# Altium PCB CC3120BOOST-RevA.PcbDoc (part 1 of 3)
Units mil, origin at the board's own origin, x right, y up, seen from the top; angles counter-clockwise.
Board outline 2300 x 1700 mil, 4 copper layers (Top Layer, Mid-Layer 1, Mid-Layer 2, Bottom Layer), stack 90 mil thick; 155 components, 108 nets, 432 pads, 292 vias.
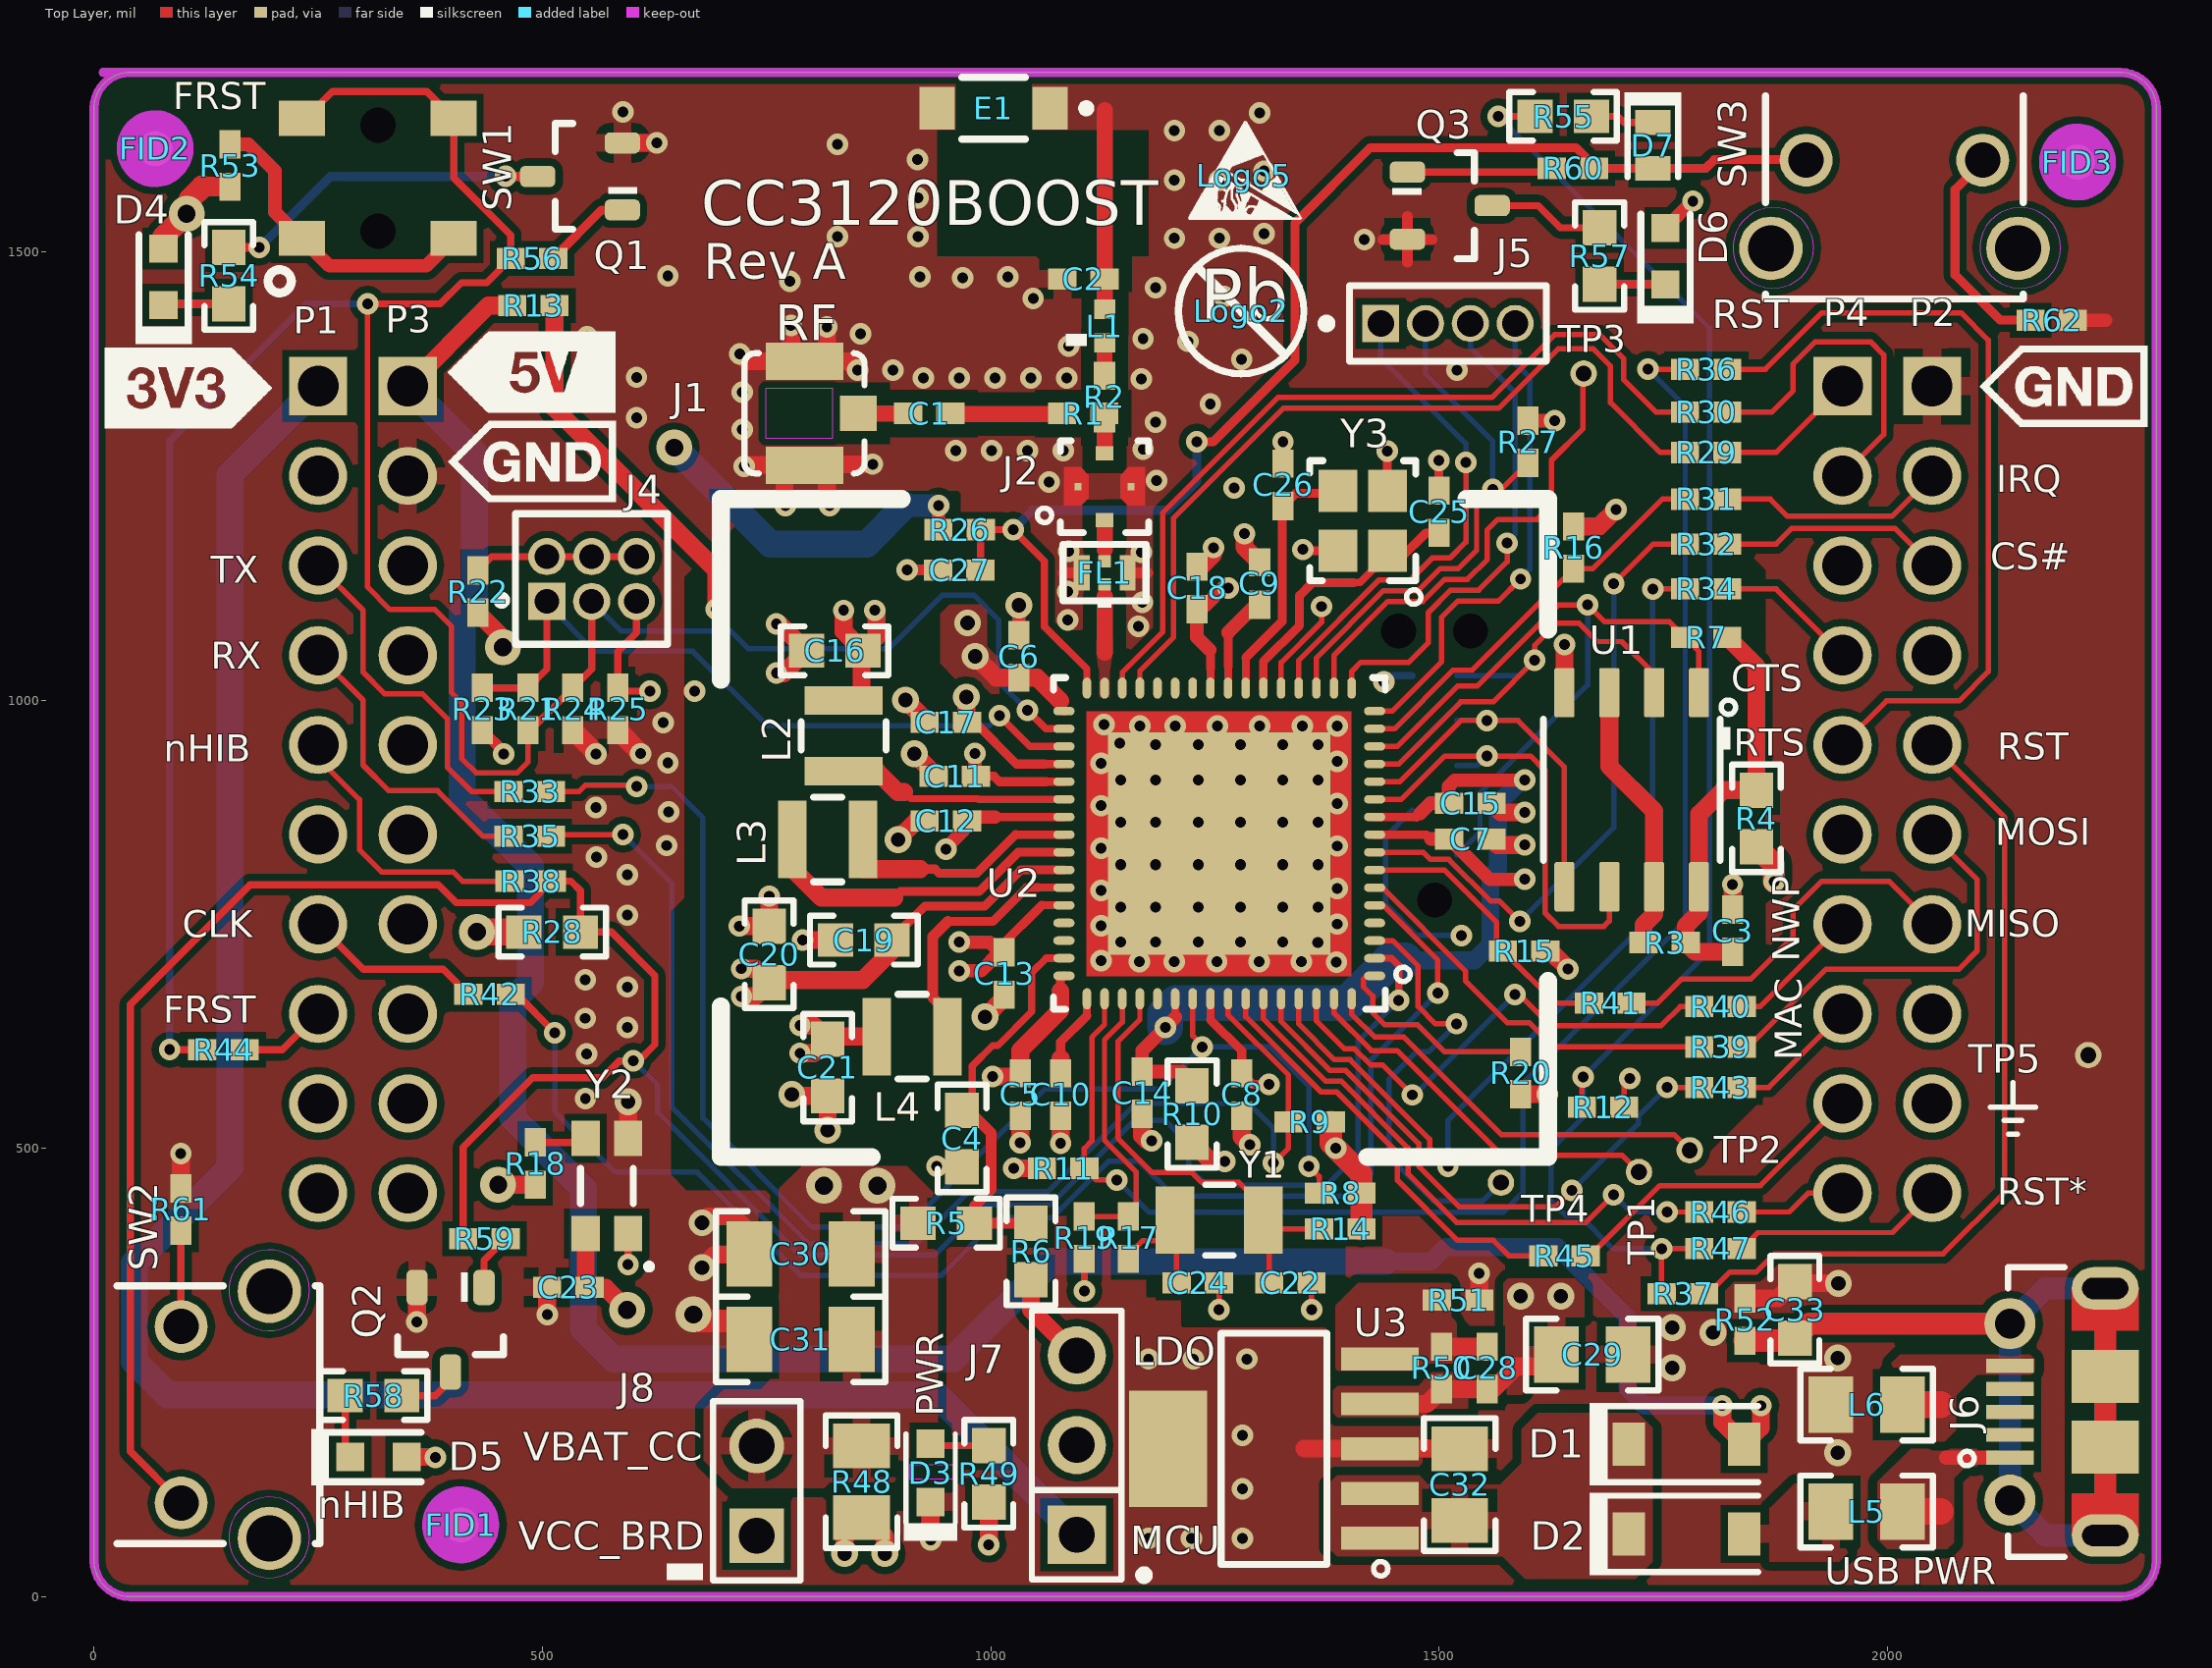
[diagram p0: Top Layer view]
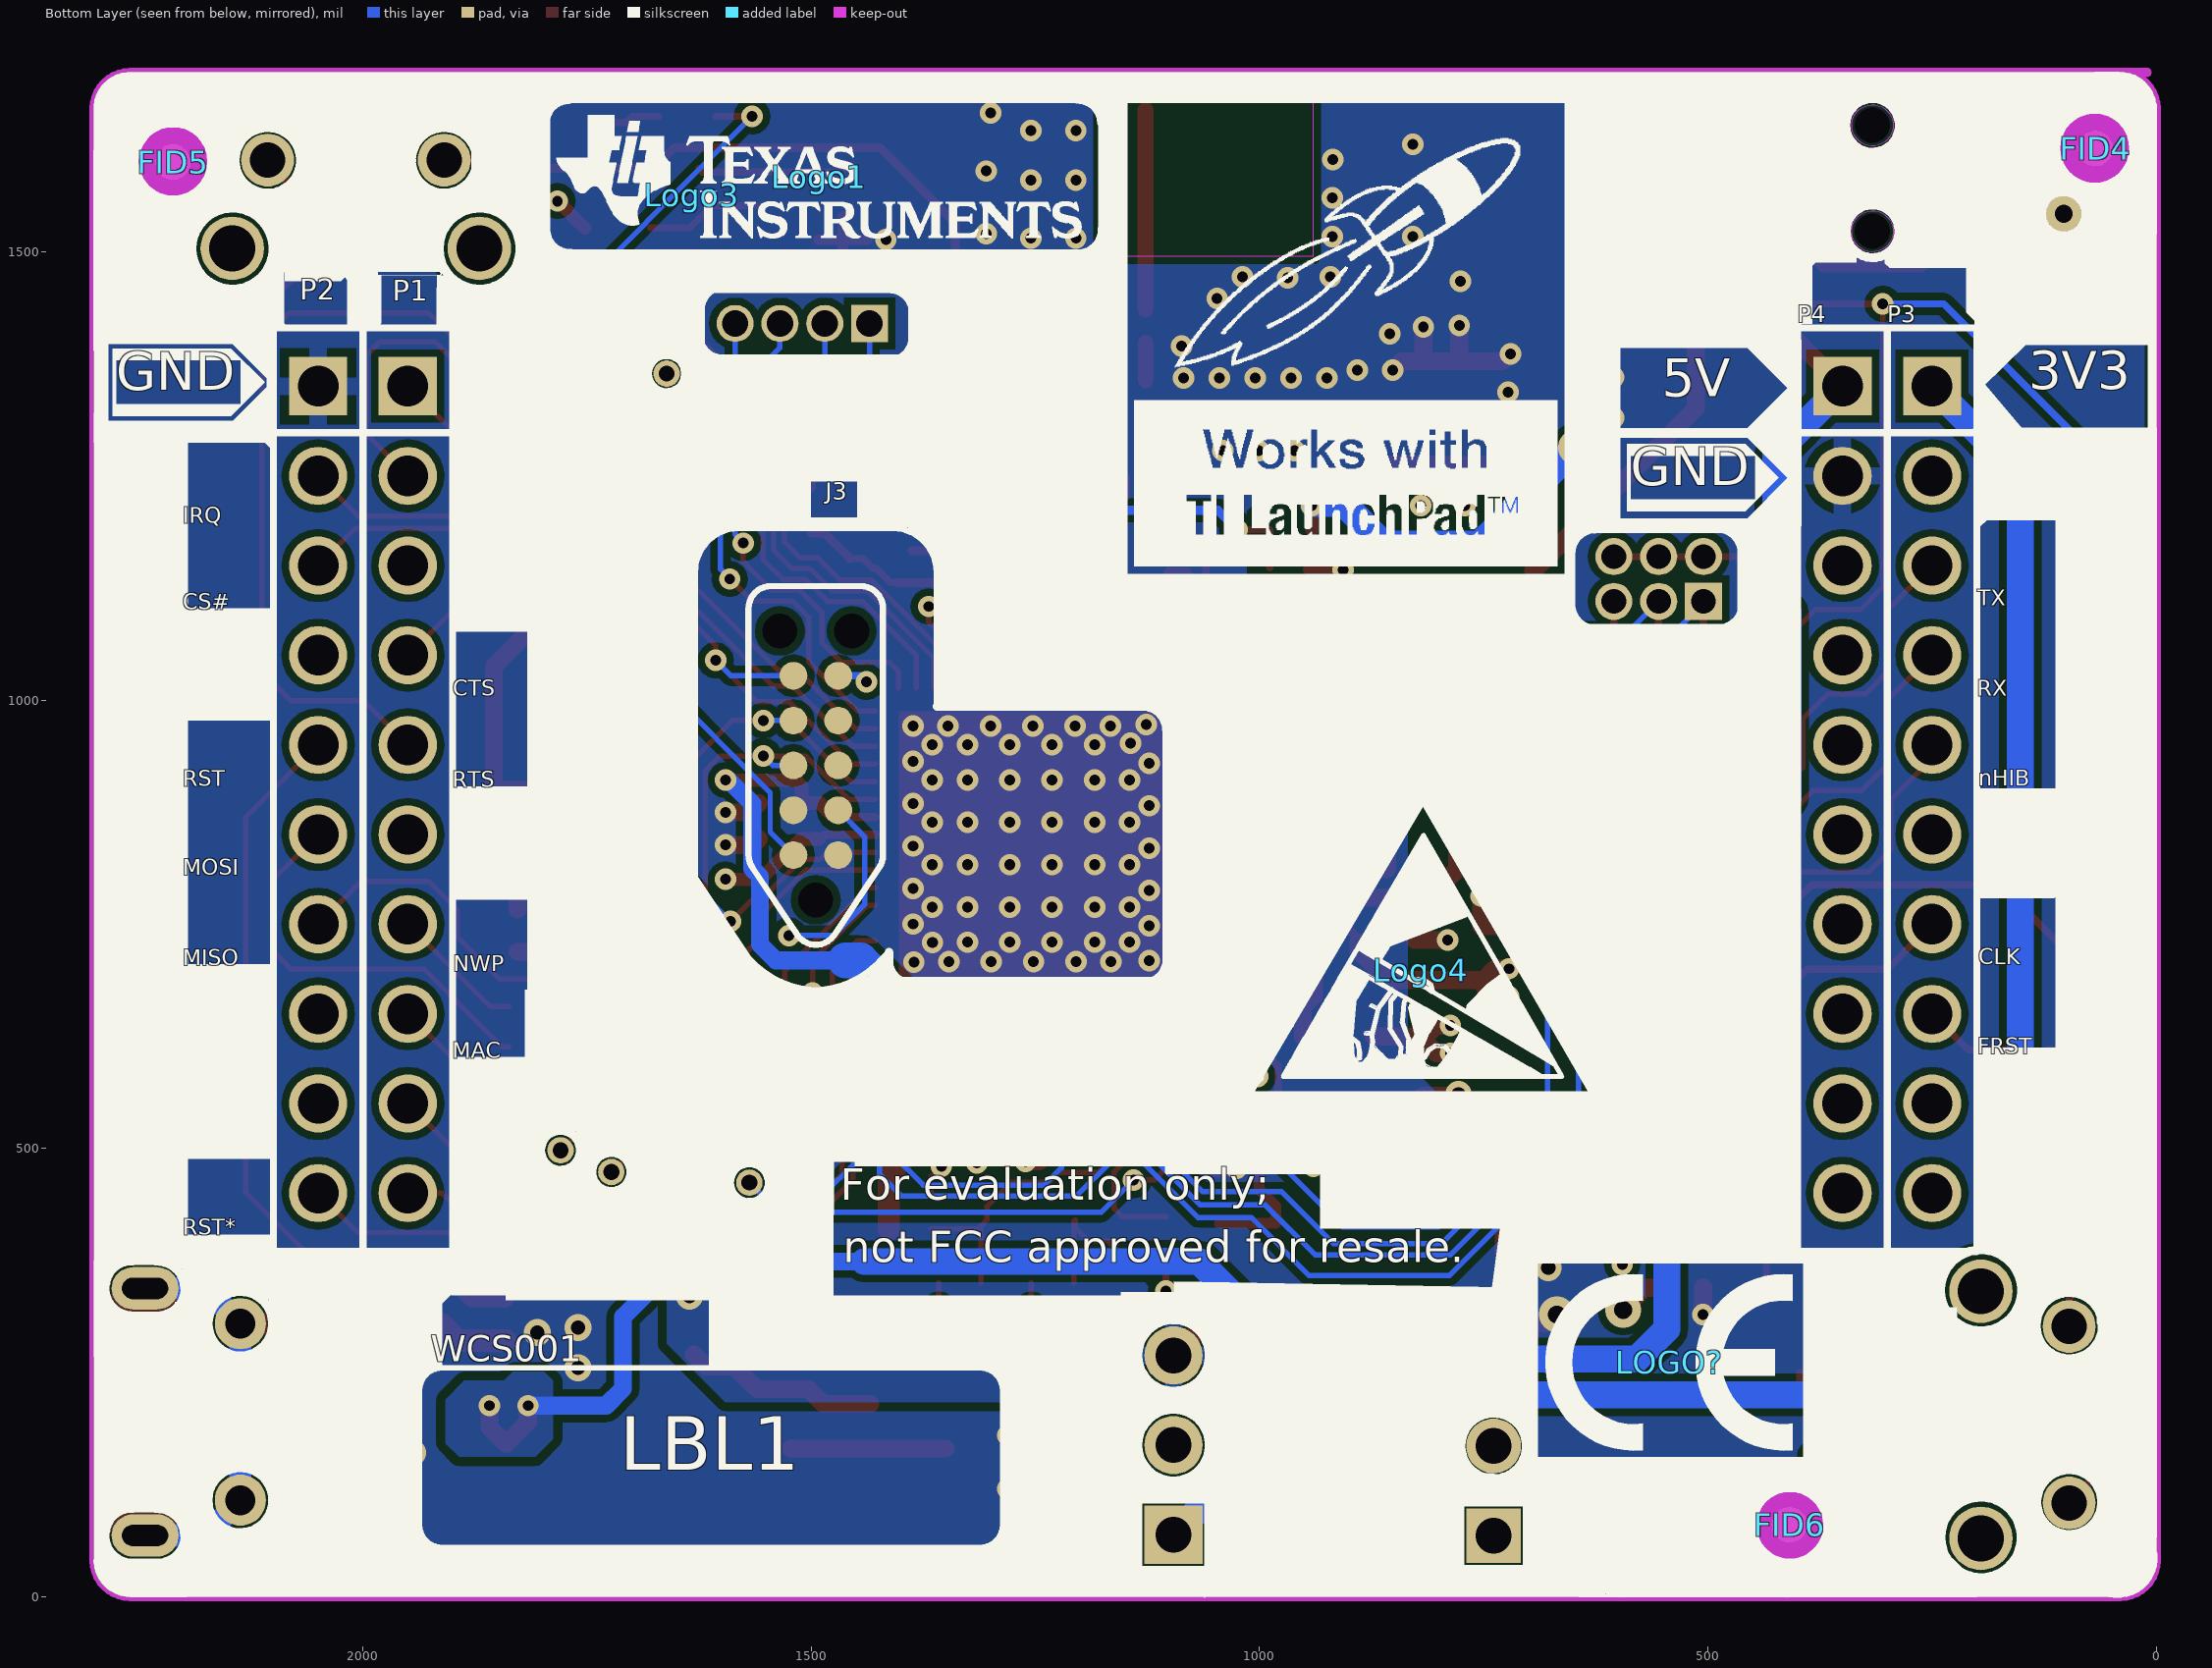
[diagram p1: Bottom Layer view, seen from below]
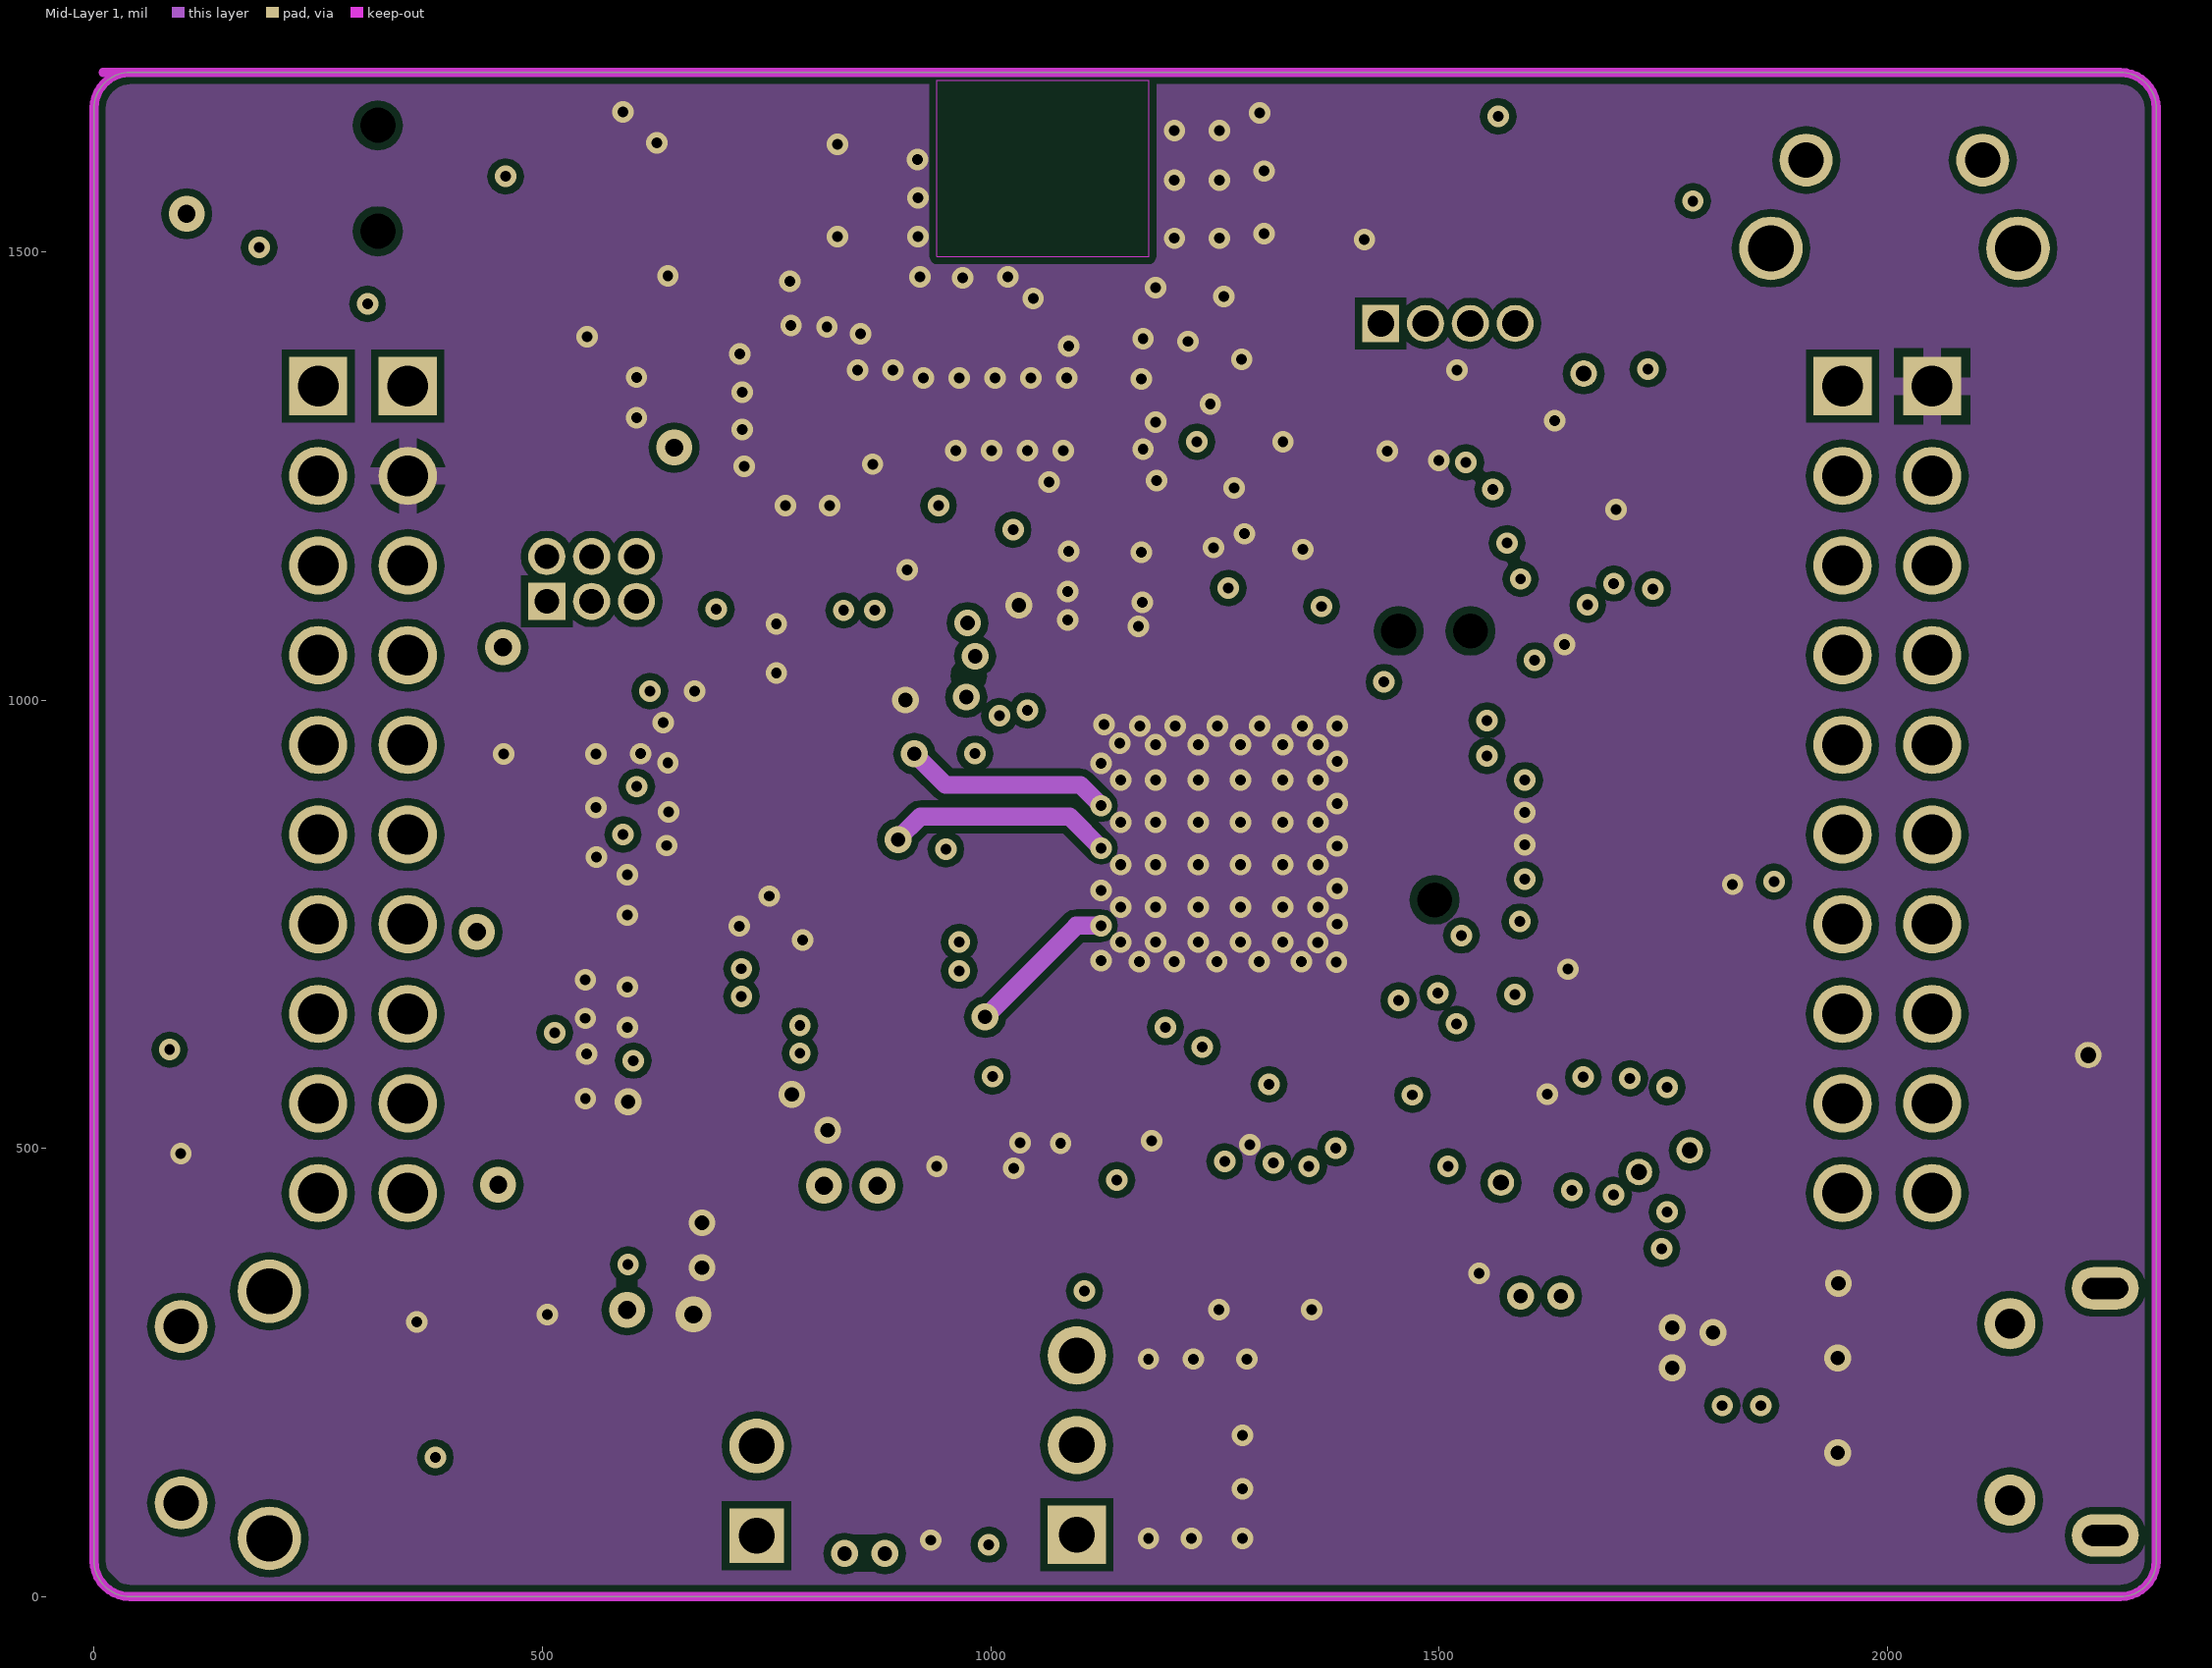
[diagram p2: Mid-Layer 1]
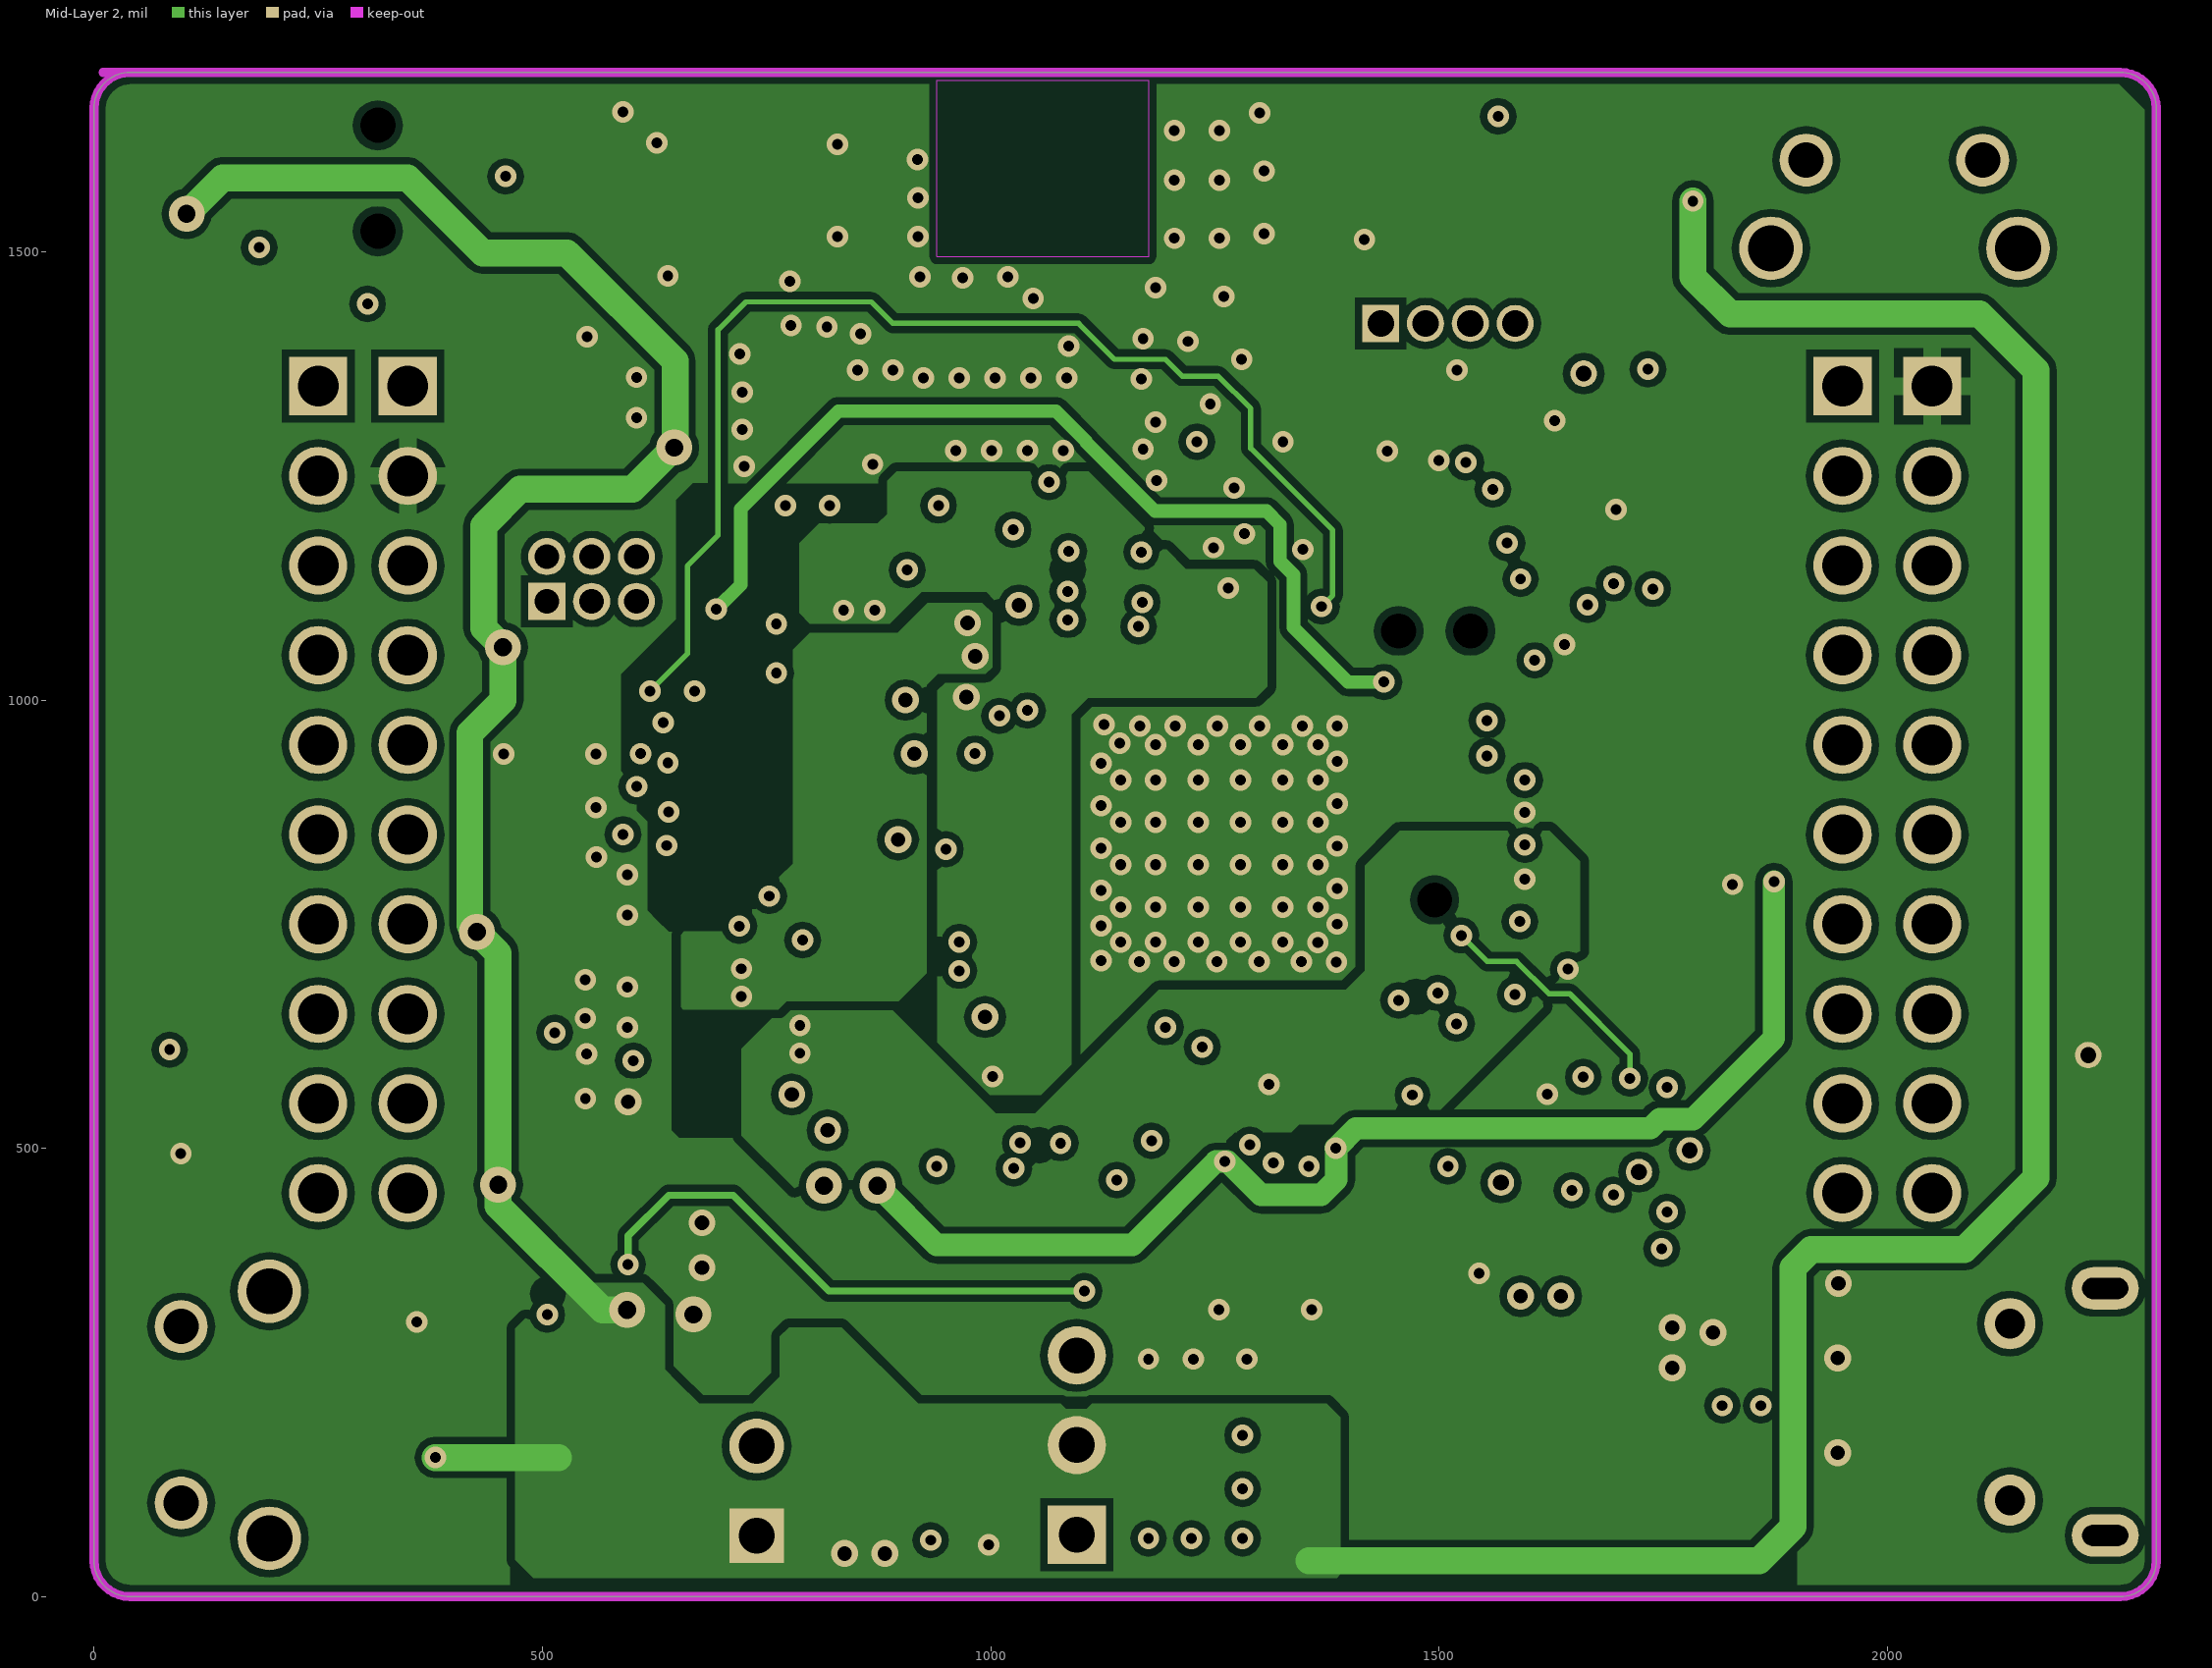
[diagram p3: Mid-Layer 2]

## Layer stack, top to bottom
Top Solder: solder mask 0.4, Solder Resist, Dk 3.5
Top Layer: signal copper 1.4
Dielectric1: core 59.2, FR-4, Dk 4.8
Mid-Layer 1: signal copper 1.4
Dielectric2: dielectric 12.6, FR-4, Dk 4.8
Mid-Layer 2: signal copper 1.4
Dielectric3: dielectric 12.6, FR-4, Dk 4.8
Bottom Layer: signal copper 1.4
Bottom Solder: solder mask 0.4, Solder Resist, Dk 3.5

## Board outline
0,40 ccw(c40,40) 40,0 2260,0 ccw(c2260,40) 2300,40 2300,1660 ccw(c2260,1660) 2260,1700 40,1700 ccw(c40,1660) 0,1660

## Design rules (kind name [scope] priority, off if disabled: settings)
AcuteAngle [All] p1: minimum=4.50000000000000E+0001 checktracksonly=TRUE
AssemblyTestPointUsage [All] p1: valid=2
Clearance Clearance_3 [InNetClass('50 ohm') vs INPOLY] p1: gap=15
Clearance Clearance_1 [inpoly vs inpoly] p2: gap=10
Clearance Clearance_Poly [InPolygon] p3: gap=7.9
Clearance Clearance_2 [iskeepout] p4: gap=0
Clearance [All] p5: gap=6
ComponentClearance ComponentClearance_MountingHoles_FiducialMarks [InComponentClass('Mounting Holes') vs InComponentClass('FiducialMark')] p1: gap=10 collisioncheckmode=3 verticalgap=10 showdistances=FALSE
ComponentClearance ComponentClearance_Shunt [InComponentClass('Header') vs InComponentClass('Shunt')] p2: gap=0 collisioncheckmode=3 verticalgap=0 showdistances=FALSE
ComponentClearance ComponentClearance_Logo [InComponentClass('Logo')] p3: gap=0 collisioncheckmode=3 verticalgap=0 showdistances=FALSE
ComponentClearance ComponentClearance_ScrewToNut [(HasFootprint('NY PMS 440 0025 PH')) vs (HasFootprint('Keystone_1902C'))] p4: gap=0 collisioncheckmode=3 verticalgap=0 showdistances=FALSE
ComponentClearance ComponentClearance_MountingHoles [InComponentClass('Mounting Holes')] p5: gap=20 collisioncheckmode=3 verticalgap=100000 showdistances=FALSE
ComponentClearance ComponentClearance_SmallPassives [HasFootprint('0201*') or HasFootprint('0402*') or HasFootprint('0508') or HasFootprint('0603*') or HasFootprint('0612') or HasFootprint('0805*') or HasFootprint('0815*') or HasFootprint('0830*') or HasFootprint('1206*') or HasFootprint('1210*') or HasFootprint('1808*') or HasFootprint('1812*') or HasFootprint('1825*') or HasFootprint('2010*') or HasFootprint('2220*') or HasFootprint('2225*') or HasFootprint('2512*') or HasFootprint('2728*') or HasFootprint('3518*') vs HasFootprint('0201*') or HasFootprint('0402*') or HasFootprint('0508') or HasFootprint('0603*') or HasFootprint('0612') or HasFootprint('0805*') or HasFootprint('0815*') or HasFootprint('0830*') or HasFootprint('1206*') or HasFootprint('1210*') or HasFootprint('1808*') or HasFootprint('1812*') or HasFootprint('1825*') or HasFootprint('2010*') or HasFootprint('2220*') or HasFootprint('2225*') or HasFootprint('2512*') or HasFootprint('2728*') or HasFootprint('3518*')] p6 off: gap=10 collisioncheckmode=3 verticalgap=10 showdistances=FALSE
ComponentClearance ComponentClearance_THtoSMT [IsThruComponent vs IsSMTComponent] p7: gap=10 collisioncheckmode=3 verticalgap=10 showdistances=FALSE
ComponentClearance ComponentClearance_THtoTH [IsThruComponent vs IsThruComponent] p8: gap=0 collisioncheckmode=3 verticalgap=10 showdistances=FALSE
ComponentClearance [All] p9 off: gap=10 collisioncheckmode=3 verticalgap=10 showdistances=FALSE
DiffPairsRouting [All] p1: maxlimit=100 minlimit=10 mostfreqgap=10 toplayer_minwidth=15 toplayer_maxwidth=15 toplayer_prefwidth=15 midlayer1_minwidth=15 midlayer1_maxwidth=15 midlayer1_prefwidth=15 midlayer2_minwidth=15 midlayer2_maxwidth=15 midlayer2_prefwidth=15 bottomlayer_minwidth=15 bottomlayer_maxwidth=15 bottomlayer_prefwidth=15 maxuncoupledlength=1000
FabricationTestPointUsage TestPointUsage [All] p1: valid=2 allowmultiple=FALSE
FabricationTestpoint Testpoint [All] p1: side=3 testpointundercomponent=TRUE minsize=40 maxsize=100 preferedsize=60 minholesize=0 maxholesize=40 preferedholesize=32 testpointgrid=1 allowsidetop=TRUE allowsidebottom=TRUE usegrid=TRUE gridtolerance=0.01
FanoutControl Fanout_LCC [IsLCC] p1: bgadir=Out bgaviamode=Centered fanoutstyle=Auto fanoutdirection=Alternating viagrid=1 // Fanout_LCC (Default Rule)
FanoutControl Fanout_BGA [IsBGA] p2: bgadir=Out bgaviamode=Centered fanoutstyle=Auto fanoutdirection=Alternating viagrid=1 // Fanout_BGA (Default Rule)
FanoutControl Fanout_Default [All] p4: bgadir=Out bgaviamode=Centered fanoutstyle=Auto fanoutdirection=Alternating viagrid=1 // Fanout_Default (Default Rule)
FanoutControl Fanout_Small [(CompPinCount < 5)] p5: bgadir=Out bgaviamode=Centered fanoutstyle=Auto fanoutdirection=OutThenIn viagrid=1 // Fanout_Small (Default Rule)
Height [All] p1: minheight=0 maxheight=1345 prefheight=500
HoleSize [All] p1: absolutevalues=TRUE maxlimit=251 minlimit=8 maxpercent=80.000 minpercent=20.000
MinimumAnnularRing MinimumAnnularRing_ThermalPadVias [IsVia and InAnyComponent] p1: minimumring=5
MinimumAnnularRing [All] p2: minimumring=5
MinimumSolderMaskSliver MinimumSolderMaskSliver_Logo [InComponentClass('Logo') vs InComponentClass('Logo')] p1: minsoldermaskwidth=0.7
MinimumSolderMaskSliver [All] p2: minsoldermaskwidth=3
PlaneConnect [All] p1: planeconnectstyle=Relief reliefexpansion=10 reliefentries=4 reliefconductorwidth=10 reliefairgap=10
PolygonConnect PolygonConnect_3 [InPadClass('SMD')] p1: connectstyle=Relief reliefconductorwidth=20 reliefentries=4 polygonreliefangle="90 Angle" airgapwidth=10
PolygonConnect [InPadClass('TH')] p2: connectstyle=Relief reliefconductorwidth=20 reliefentries=4 polygonreliefangle="90 Angle" airgapwidth=10
PolygonConnect PolygonConnect_1 [InPadClass('PLANECLASS')] p3: connectstyle=Direct reliefconductorwidth=10 reliefentries=4 polygonreliefangle="90 Angle" airgapwidth=10
PolygonConnect PolygonConnect_2 [All] p4: connectstyle=Direct reliefconductorwidth=10 reliefentries=4 polygonreliefangle="90 Angle" airgapwidth=10
RoutingVias ThermalPadVias [IsVia and InAnyComponent] p1: holewidth=7.87 width=24 viastyle="Through Hole" minholewidth=7.87 minwidth=24 maxholewidth=12.99 maxwidth=24
RoutingVias [All] p2: holewidth=16 width=34 viastyle="Through Hole" minholewidth=7.87 minwidth=24 maxholewidth=40 maxwidth=65
SilkToSilkClearance SilkToSilkClearance_Pb-FreeLogo [(HasFootprint('Pb-Free_Overlay_Medium') OR HasFootprint('Pb-Free_Overlay_Small')) vs (HasFootprint('Pb-Free_Overlay_Medium') OR HasFootprint('Pb-Free_Overlay_Small'))] p1: silktosilkclearance=0
SilkToSilkClearance [All] p2: silktosilkclearance=3
SilkToSolderMaskClearance "Silk to Solder Mask Opening" [IsPad] p1: minsilkscreentomaskgap=1 clearancetoexposedcopper=TRUE
SolderMaskExpansion SolderMaskExpansion_1 [InPadClass('SM')] p1: expansion=2.5
SolderMaskExpansion [All] p2: expansion=0
Width [All] p1: maxlimit=100 minlimit=6 preferedwidth=10 checkconnectedcopper=TRUE
15 further rules are at their usual default settings.

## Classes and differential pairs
pad class SMD: C2-1 C2-2 C3-1 C3-2 C4-1 C4-2 C5-1 C5-2 C6-1 C6-2 C7-1 C7-2 C9-1 C9-2 C10-1 C10-2 C11-1 C11-2 C12-1 C12-2 C13-1 C13-2 C14-1 C14-2 C16-1 C16-2 C18-1 C18-2 C20-1 C20-2 C21-1 C21-2 C22-1 C22-2 C23-1 C23-2 C25-1 C25-2 C26-1 C26-2 C27-1 C27-2 C28-1 C28-2 C29-1 C29-2 C30-1 C30-2 C31-1 C31-2 C32-1 C32-2 D3-1 D3-2 D4-1 D4-2 L7-1 L7-2 L8-1 L8-2 Q1-1 Q1-2 Q1-3 Q2-1 Q2-2 Q2-3 Q3-1 Q3-2 Q3-3 R2-1 R2-2 R3-1 R3-2 R4-1 R4-2 R5-1 R5-2 R6-1 R6-2 R7-1 R7-2 R8-1 R8-2 R10-1 R10-2 R11-1 R11-2 R12-1 R12-2 R13-1 R13-2 R14-1 R14-2 R15-1 R15-2 R16-1 R16-2 R17-1 R17-2 R18-1 R18-2 R19-1 R19-2 R20-1 R20-2 R21-1 R21-2 R22-1 R22-2 R23-1 R23-2 R24-1 R24-2 R25-1 R25-2 R26-1 R26-2 R28-1 R28-2 R29-1 R29-2 R31-1 R31-2 R32-1 R32-2 R33-1 R33-2 R34-1 R34-2 R36-1 R36-2 R38-1 R38-2 R39-1 R39-2 R40-1 R40-2 R41-1 R41-2 R42-1 R42-2 R43-1 R43-2 R44-1 R44-2 R45-1 R45-2 R46-1 R46-2 R48-1 R48-2 R54-1 R54-2 R55-1 R55-2 R56-1 R56-2 R57-1 R57-2 R58-1 R58-2 R59-1 R59-2 R60-1 R60-2 R286-1 R286-2 R290-1 R290-2 R295-1 R295-2 R297-1 R297-2 TP1-1 U4-6
pad class PLANECLASS: C1-1 C1-2 E1-1 E1-2 FL1-1 FL1-2 FL1-3 FL1-4 J2-1 J2-2 J2-3 J3-1 J3-2 J3-3
pad class "New Class": SW1-3 SW1-MH1
component class Logo: Logo1
component class Label: LBL1
component class Header: J4 J5 J7 J8
component class FiducialMark: FID1 FID2 FID3 FID4 FID5 FID6
component class AssemblyNote: ZZ2 ZZ3 ZZ4
pad class TH: J6-1 J6-2 J7-10 J7-11 J8-2 J8-3 P1-1 P1-2 P1-3 P1-4 P1-5 P1-6 P1-7 P1-8 P1-9 P1-10 P2-1 P2-2 P2-3 P2-4 P2-5 P2-6 P2-7 P2-8 P2-9 P2-10 P3-1 P3-2 P3-3 P3-4 P3-5 P3-6 P3-7 P3-8 P3-9 P3-10 P4-1 P4-2 P4-3 P4-4 P4-5 P4-6 P4-7 P4-8 P4-9 P4-10 SW2-1 SW2-2 SW3-1 SW3-2
component class 1.Engine: C1 C2 C3 C4 C5 C6 C7 C8 C9 C10 C11 C12 C13 C14 C15 C16 C17 C18 C19 C20 C21 C22 C23 C24 C25 C26 C27 E1 FL1 J1 J2 J3 J4 J5 L1 L2 L3 L4 R1 R2 R3 R4 R5 R6 R7 R8 R9 R10 R11 R12 R13 R14 R15 R16 R17 R18 R19 R20 R21 R22 R23 R24 R25 R26 R27 TP1 TP2 TP3 TP4 U1 U2 Y1 Y2 Y3
component class "2.HOST INTERFACE": C28 C29 C30 C31 C32 C33 D1 D2 D3 D4 D5 D6 D7 J6 J7 J8 L5 L6 P1 P2 P3 P4 Q1 Q2 Q3 R28 R29 R30 R31 R32 R33 R34 R35 R36 R37 R38 R39 R40 R41 R42 R43 R44 R45 R46 R47 R48 R49 R50 R51 R52 R53 R54 R55 R56 R57 R58 R59 R60 R61 R62 SW1 SW2 SW3 TP5 U3
pad class SM: J4-1 J4-2 J4-3 J4-4 J4-5 J4-6 J5-1 J5-2 J6-1 J6-2 J7-6 J7-9 J7-10 J7-11 J8-1 J8-2 J8-3
component class EVM_Hardware: FID1 FID2 FID3 FID4 FID5 FID6 LBL1 Logo1 Logo2 Logo3 Logo4 Logo5 LOGO? ZZ2 ZZ3 ZZ4
net class "50 ohm": NetC1_2 NetFL1_1 NetFL1_3 NetJ2_2

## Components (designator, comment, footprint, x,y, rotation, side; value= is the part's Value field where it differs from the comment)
C1 "500R07S100JV4T" 0402#1 931.5,1319.75 r180 top
C2 "GRM1555C1HR50BA01D" 0402#1 1103.43,1469.57 r0 top locked
C3 "C1005X5R1A104K050BA" 0402#1 1827.5,742.67 r90 top locked
C4 "GRM188R60J106ME47D" 0603 968,511 r270 top locked
C5 "C1005X5R1A104K050BA" 0402#1 1033,560 r270 top locked
C6 "C1005X5R1A105K050BB" 0402#1 1031.6,1048.7 r90 top
C7 "C1005X5R1A104K050BA" 0402#1 1535,845 r0 top locked
C8 "C1005X5R1A104K050BA" 0402#1 1280,560 r270 top locked
C9 "C1005X5R1A104K050BA" 0402#1 1300,1130 r90 top locked
C10 "C1005X5R1A104K050BA" 0402#1 1078,560 r270 top locked
C11 "C1005X5R0J475M050BC" 0402#1 960,915 r180 top locked
C12 "C1005X5R0J475M050BC" 0402#1 950,865 r180 top locked
C13 "C1005X5R0J475M050BC" 0402#1 1015,695 r270 top
C14 "C1005X5R1A104K050BA" 0402#1 1168.99,561.99 r270 top locked
C15 "C1005X5R1A104K050BA" 0402#1 1535,885 r0 top locked
C16 "GRM188R60J106ME47D" 0603 826,1055 r180 top
C17 "C1005X5R1A104K050BA" 0402#1 950,975 r180 top
C18 "C1005X5R1A104K050BA" 0402#1 1230,1125 r90 top locked
C19 "C1608X5R0G226M080AA" 0603 858.5,732.2 r180 top
C20 "C1608X5R0G226M080AA" 0603 753,716.4 r90 top
C21 "GRM188R60J106ME47D" 0603 818.2,590 r270 top
C22 "500R07S100JV4T" 0402#1 1334.2,350 r0 top locked
C23 "C1005X5R1A104K050BA" 0402#1 529,345 r180 top locked
C24 "500R07S100JV4T" 0402#1 1231.04,350 r0 top locked
C25 "GRM1555C1H6R2CA01D" 0402#1 1500,1210 r90 top locked
C26 "GRM1555C1H6R2CA01D" 0402#1 1326,1240 r90 top locked
C27 "C1005X5R1A104K050BA" 0402#1 965,1145 r180 top locked
C28 "GRM1555C1H150JA01D" 0402#1 1554,255 r90 top locked
C29 "GRM21BR61A106KE19L" 0805_HV 1671,270 r0 top locked
C30 "GRM31CR60J107ME39L" 1206 788,382 r180 top locked
C31 "GRM31CR60J107ME39L" 1206 788,287 r180 top locked
C32 "GRM21BR61A106KE19L" 0805_HV 1523,125 r90 top locked
C33 "GRM188R61H102KA01D" 0603 1897,320 r90 top locked
D1 "MBR130T1G" SOD-123 1776,170 r0 top locked
D2 "MBR130T1G" SOD-123 1776,70 r0 top locked
D3 "SML-311UTT86" SML-31_Red 933,138 r90 top locked
D4 "150060RS75000" WL-SMCW_RED 77.5,1472 r90 top
D5 "150060GS75000" WL-SMCW_GREEN 317.3,155.7 r0 top
D6 "150060YS75000" WL-SMCW_YELLOW 1752.62,1494.98 r90 top
D7 "CD0603-B00340" Diode_0603 1738.68,1618.59 r270 top
E1 "AH316M245001-T" TAYO_AH316M 1003.19,1660 r180 top locked
FID1 "Fiducial" Fiducial10-20 409,80 r90 top locked
FID2 "Fiducial" Fiducial10-20 68,1615 r90 top locked
FID3 "Fiducial" Fiducial10-20 2212,1600 r90 top locked
FID4 "Fiducial" Fiducial10-20 68,1615 r90 bottom locked
FID5 "Fiducial" Fiducial10-20 2212,1600 r90 bottom locked
FID6 "Fiducial" Fiducial10-20 409,80 r90 bottom locked
FL1 "DEA202450BT-1294C1-H" TDK_DEA202450BT-1294C1-H 1127.05,1142 r180 top locked
J1 "U.FL-R-SMT-1" CONN_UFL-R-SMT-1 792.33,1319.75 r180 top
J2 "MM8030-2610RJ3" MURATA_MM8030-2610 1127.05,1237.97 r90 top locked
J3 "TC2050-IDC-430-FP" TC2050-IDC-430-FP 1495,927.08 r0 bottom
J4 "GRPB032VWVN-RC" Sullins_GRPB032VWVN-RC 555,1135 r90 top
J5 "GRPB041VWVN-RC" Sullins_GRPB041VWVN-RC 1510,1420 r0 top locked
J6 "105017-0001" CONN_105017-0001 2189.93,206 r90 top locked
J7 "TSW-103-07-G-S" TSW-103-07-G-S 1096,169 r90 top locked
J8 "HMTSW-102-07-G-S-240" SAMTEC_HMTSW-102-07-G-S-240 739,118 r90 top locked
L1 "3.3nH" IND_LQG15H 1127.05,1417.07 r90 top locked
L2 "LQM2HPN2R2MG0L" 1008 836,960 r270 top
L3 "LQM2HPN1R0MG0L" 1008 818.2,844.4 r0 top
L4 "LQM2HPN2R2MG0L" 1008 912.4,624.6 r0 top
L5 "MMZ2012R300A" 0805_HV 1977,95 r180 top locked
L6 "MMZ2012R300A" 0805_HV 1977,214 r0 top locked
LBL1 "Size: 0.65\" x 0.20 \"" Label_650x200 1611.8,155 r0 bottom
Logo1 "Texas Instruments" TI_Stacked_Overlay_Small 1491.3,1583.6 r180 bottom
Logo2 "Pb-Free Symbol" Pb-Free_Overlay_Small 1279.3,1433.9 r0 top
Logo3 "FCC disclaimer" FCC_disclaimer 1633,1563 r180 bottom
Logo4 "ESD Susceptible" ESD_Overlay_Small 820.2,698.8 r180 bottom
Logo5 "ESD Susceptible" ESD_Overlay_Small 1282.9,1584.8 r0 top
LOGO? "CE Mark" CE_Mark_5mm 543.3,261.3 r180 bottom
P1 "SSW-110-23-F-S" CONN_SSW-110-23-F-S 1950,900 r90 bottom locked
P2 "SSW-110-23-F-S" CONN_SSW-110-23-F-S 2050,900 r90 bottom locked
P3 "SSW-110-23-F-S" CONN_SSW-110-23-F-S 250,900 r90 bottom locked
P4 "SSW-110-23-F-S" CONN_SSW-110-23-F-S 350,900 r90 bottom locked
Q1 "BSS138" SOT-23 542,1584 r180 top
Q2 "BSS138" SOT-23 397.53,297.6 r270 top
Q3 "BSS138" SOT-23 1512.08,1551.43 r0 top
R1 "ERJ-2GE0R00X" 0402#1 1103.16,1319.75 r180 top
R2 "ERJ-2GE0R00X" 0402#1 1127,1338 r270 top locked
R3 "CRCW040210K0JNED" 0402#1 1751.71,729.57 r180 top locked
R4 "RC0603JR-070RL" 0603 1854,868 r270 top
R5 "RC0603JR-070RL" 0603 950.43,416.59 r180 top
R6 "RC0603JR-070RL" 0603 1045,385 r270 top locked
R7 "CRCW0402100KJNED" 0402#1 1798,1070 r180 top locked
R8 "CRCW0402100KJNED" 0402#1 1390,450 r180 top locked
R9 "CRCW0402100KJNED" 0402#1 1355.71,529.34 r180 top locked
R10 "RC0603JR-070RL" 0603 1224.64,538.22 r270 top locked
R11 "CRCW0402100KJNED" 0402#1 1080.9,477.7 r180 top
R12 "ERJ-2GE0R00X" 0402#1 1683,546 r180 top
R13 "ERJ-2GE0R00X" 0402#1 490,1440 r0 top
R14 "CRCW0402100KJNED" 0402#1 1390,410 r180 top locked
R15 "CRCW0402100KJNED" 0402#1 1595,720 r0 top locked
R16 "CRCW0402100KJNED" 0402#1 1650,1170 r90 top locked
R17 "ERJ-2GE0R00X" 0402#1 1153.5,400.4 r90 top
R18 "CRCW04021K00JNED" 0402#1 492,483 r90 top
R19 "ERJ-2GE0R00X" 0402#1 1104.5,400.4 r90 top
R20 "CRCW0402100KJNED" 0402#1 1591,584 r270 top locked
R21 "ERJ-2GE0R00X" 0402#1 484,990 r270 top locked
R22 "CRCW04021K00JNED" 0402#1 428,1121 r90 top locked
R23 "CRCW0402100KJNED" 0402#1 433,990 r270 top locked
R24 "CRCW0402100KJNED" 0402#1 534,990 r270 top locked
R25 "CRCW0402100KJNED" 0402#1 584,990 r270 top locked
R26 "CRCW0402100KJNED" 0402#1 965.39,1190 r0 top locked
R27 "CRCW0402100KJNED" 0402#1 1599,1288 r90 top
R28 "CRCW0603100KFKEA" 0603 511.03,741.22 r180 top
R29 "ERJ-2GE0R00X" 0402#1 1798,1276 r0 top locked
R30 "ERJ-2GE0R00X" 0402#1 1798,1321 r0 top locked
R31 "ERJ-2GE0R00X" 0402#1 1798,1224 r180 top locked
R32 "ERJ-2GE0R00X" 0402#1 1798,1174 r180 top locked
R33 "ERJ-2GE0R00X" 0402#1 486,898 r180 top locked
R34 "ERJ-2GE0R00X" 0402#1 1798,1124 r0 top locked
R35 "ERJ-2GE0R00X" 0402#1 486,848 r180 top locked
R36 "ERJ-2GE0R00X" 0402#1 1798,1369 r0 top locked
R37 "ERJ-2GE0R00X" 0402#1 1772,338 r180 top locked
R38 "CRCW04021K00JNED" 0402#1 487,798 r180 top locked
R39 "ERJ-2GE0R00X" 0402#1 1814,613 r180 top locked
R40 "ERJ-2GE0R00X" 0402#1 1814,658 r0 top locked
R41 "ERJ-2GE0R00X" 0402#1 1691,662 r180 top
R42 "ERJ-2GE0R00X" 0402#1 441.1,671.74 r180 top locked
R43 "ERJ-2GE0R00X" 0402#1 1814,568 r0 top locked
R44 "CRCW04021K00JNED" 0402#1 144.38,610 r0 top
R45 "ERJ-2GE0R00X" 0402#1 1640,380 r0 top locked
R46 "ERJ-2GE0R00X" 0402#1 1814,429 r0 top locked
R47 "ERJ-2GE0R00X" 0402#1 1814,388 r180 top locked
R48 "CRM0805-FX-R100ELF" 0805_HV 856,128 r90 top locked
R49 "CRCW0603270RJNEA" 0603 998,137 r90 top locked
R50 "CRCW040251K0JNED" 0402#1 1503,255 r270 top locked
R51 "CRCW040230K1FKED" 0402#1 1521.29,330.95 r180 top locked
R52 "CRCW0402100KJNED" 0402#1 1841,309 r90 top locked
R53 "ERJ-2RKF1000X" 0402#1 151.4,1596.2 r270 top
R54 "CRCW0603270RJNEA" 0603 150.3,1473.2 r90 top
R55 "ERJ-3GEY0R00V" 0603 1638.5,1651 r180 top locked
R56 "CRCW040210K0JNED" 0402#2 488.5,1492.5 r0 top
R57 "CRCW0603270RJNEA" 0603 1679.21,1495.24 r90 top
R58 "CRCW0603220RJNEA" 0603 311.75,224.23 r0 top
R59 "CRCW040210K0JNED" 0402#1 435.4,399.3 r0 top
R60 "CRCW040210K0JNED" 0402#1 1649.5,1593 r180 top locked
R61 "ERJ-2RKF1000X" 0402#1 96.86,431.79 r270 top
R62 "ERJ-2RKF1000X" 0402#1 2183.46,1423.66 r180 top
SW1 "EVQ-PSD02K" SW_EVQ-PSD02K 316.5,1581.9 r90 top
SW2 "MJTP1117" SW_MJTP1117 19.6,202.8 r270 top
SW3 "MJTP1117" SW_MJTP1117 2008,1679.8 r180 top
TP1 "TESTPOINT" TP_H045P075#1 1723,473.6 r90 top
TP2 "TESTPOINT" TP_H045P075#1 1779.7,497.8 r90 top
TP3 "TESTPOINT" TP_H045P075#1 1661.4,1364.1 r90 top
TP4 "TESTPOINT" TP_H045P075#1 1569.1,461.7 r90 top
TP5 "TESTPOINT" TP_H045P075#2 2224.1,604 r270 top
U1 "MX25R1635FM1IL0" SOP-8_150MIL 1715,900 r270 top locked
U2 "CC3120RNMARGKR" RGK0064B 1255,840 r180 top locked
U3 "TPS79601DCQR" DCQ0006A_N 1316,165 r180 top
Y1 "ABS07-32.768KHZ-9-T" XTAL_ABS07 1255,420 r0 top locked
Y2 "OV-7604-C7" MC_OV-7604-C7 572,458 r180 top locked
Y3 "Q24FA20H0039600" Epson_FA-20H 1415,1200 r180 top locked
ZZ2 "These assemblies are ESD sensitive, ESD precautions shall be observed." AssemblyNote 44.3,3153.2 r0 top
ZZ3 "These assemblies must be clean and free from flux and all contaminants. Use of no clean flux is not acceptable." AssemblyNote 41,3038.2 r0 top
ZZ4 "These assemblies must comply with workmanship standards IPC-A-610 Class 2, unless otherwise specified." AssemblyNote 44.2,2926.3 r0 top

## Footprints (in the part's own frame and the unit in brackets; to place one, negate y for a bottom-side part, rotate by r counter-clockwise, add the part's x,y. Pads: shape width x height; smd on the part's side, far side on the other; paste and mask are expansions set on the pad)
0402#1 [mm] "0402 from SM-752 data"
  rect 0.8x0.6 smd: 1(-0.6,0) 2(0.6,0)
  body extent -0.55,-0.3 0.55,0.3, height 0.6
0402#2 [mm] "0402 from SM-752 data"
  rect 0.8x0.6 smd mask+0: 1(-0.6,0) 2(0.6,0)
  body extent -0.55,-0.3 0.55,0.3, height 0.6
0603 [mm] "0603 from SM-752 data"
  rect 1x0.95 smd: 1(-0.8,0) 2(0.8,0)
  silkscreen extent -1.52,-0.69 1.52,0.69, body extent -0.87,-0.47 0.87,0.47, height 0.85
0805_HV [mil] "0805 with 30mil clearance between pads"
  rect 50x63 smd: 1(-40,0) 2(40,0)
  silkscreen extent -74,-40 74,40, body extent -43,-29 43,29, height 43
1008 [mm] "SMD, Body 2.5x2mm, Height 1.2mm"
  rect 0.8x2.2 smd: 1(-1,0) 2(1,0)
  silkscreen extent -0.4,-1.2 0.4,1.2, body extent -1.35,-1.1 1.35,1.1, height 1.2
1206 [mm]
  rect 1.3x1.85 smd: 1(-1.45,0) 2(1.45,0)
  silkscreen extent -2.4,-1.21 2.4,1.21, body extent -1.7,-0.9 1.7,0.9, height 1.35
AssemblyNote [mil] "Assembly Note"
CE_Mark_5mm [mil] "Minimum text height for CE Mark"
  silkscreen extent -138,-98 138,98
CONN_105017-0001 [mm] "Molex Micro USB-B"
  rect 0.4x1.35 smd: 1(-1.3,1.35) 2(-0.65,1.35) 3(0,1.35) 4(0.65,1.35) 5(1.3,1.35)
  oval 1.2x1.9 hole 0.6 slot 1.3 at 90 deg: 6(-3.5,-1.35) 9(3.5,-1.35)
  rect 1.5x1.9 smd: 7(-1,-1.35) 8(1,-1.35)
  round 1.45 hole 0.85: 10(2.5,1.35) 11(-2.5,1.35)
  Top Layer region: -3.5,-2.298 -2.3,-2.298 -2.3,-0.398 -3.5,-0.398
  Top Layer region: 3.499,-0.399 2.299,-0.399 2.299,-2.299 3.499,-2.299
  silkscreen extent -4.1,-0.2 4.1,1.4, body extent -4.1,-3.93 4.1,1.5, height 2.72
CONN_SSW-110-23-F-S [mm] "SAMTEC"
  rect 1.65x1.65 hole 1.15 mask+0.064: 1(11.43,0)
  round 1.65 hole 1.15 mask+0.064: 2(8.89,0) 3(6.35,0) 4(3.81,0) 5(1.27,0) 6(-1.27,0) 7(-3.81,0) 8(-6.35,0) 9(-8.89,0) 10(-11.43,0)
  silkscreen extent -13.08,-1.27 13.08,1.27, body extent -13,-1.27 13,1.27, height 8.59
CONN_UFL-R-SMT-1 [mm] "Hirose recommended land pattern http://www.hirose.co.jp/cataloge_hp/e32119372.pdf 2009.2"
  rect 1.05x1 smd: 1(-1.525,0)
  rect 2.2x1.05 smd: 2(0,1.475) 3(0,-1.475)
  Top Layer keep-out region: -0.8,-0.7 1.1,-0.7 1.1,0.7 -0.8,0.7
  silkscreen extent -1.7,-1.7 1.7,1.7, body extent -1.55,-1.5 1.55,1.5, height 1.27
DCQ0006A_N [mm]
  rect 2.2x0.65 smd: 1(-3,2.54) 2(-3,1.27) 3(-3,0) 4(-3,-1.27) 5(-3,-2.54)
  rect 2.2x3.3 smd: 6(3,0)
  silkscreen extent -1.5,-3.27 1.5,3.27, body extent -3.48,-3.25 3.48,3.25, height 1.64
Diode_0603 [mm] "Based on Bourns recommended land pattern Rev 10/09"
  rect 0.7x1 smd: 1(-0.65,0) 2(0.65,0)
  silkscreen extent -1.5,-0.8 0.9,0.8, body extent -0.9,-0.5 0.9,0.5, height 0.85
Epson_FA-20H [mm]
  rect 1.1x1.2 smd: 1(-0.7,0.85) 2(-0.7,-0.85) 3(0.7,-0.85) 4(0.7,0.85)
  silkscreen extent -1.5,-1.7 1.5,1.7, body extent -1.05,-1.3 1.05,1.3, height 0.56
ESD_Overlay_Small [mil]
  silkscreen extent -156,-121 160,153
FCC_disclaimer [mil]
Fiducial10-20 [mm]
  round 1 smd mask+0.5: 1(0,0)
  Top Layer keep-out circle w1.178: c0,0 r0.5
IND_LQG15H [mm] "MuRata"
  rect 0.55x0.6 smd: 1(-0.475,0) 2(0.475,0)
  silkscreen extent -0.56,0.5 -0.21,1.1, body extent -0.52,-0.27 0.52,0.27, height 0.55
Label_650x200 [mil] "Thermal Transfer Label"
  round 1 on Mech14: 0(0,0)
  silkscreen extent -325,-100 325,100, body extent -325,-100 325,100, height 1
MC_OV-7604-C7 [mm] "MICRO CRYSTAL"
  rect 0.8x1 smd: 1(-0.6,1.35) 2(-0.6,-1.35) 3(0.6,-1.35) 4(0.6,1.35)
  silkscreen extent -1.23,-0.5 0.75,2.33, body extent -0.75,-1.6 0.75,1.6, height 1.01
MURATA_MM8030-2610 [mm] "Coaxial Connectors with Switch, SMD"
  rect 0.4x0.5 smd paste-0.5: 1(-0.95,0) 2(0.95,0)
  rect 0.2x0.2 smd: 3(0,0.75)
  rect 0.2x0.2 smd paste-0.2: 4(0,-0.75)
  silkscreen extent -1.3,-1.25 1.3,1.25, body extent -1.15,-1.1 1.15,1.1, height 1
Pb-Free_Overlay_Small [mil]
  silkscreen extent -70,-70 70,70
RGK0064B [mm] "QFN, 9.0x9.0"
  rrect100% 0.6x0.24 smd: 1(-4.4,3.75) 2(-4.4,3.25) 3(-4.4,2.75) 4(-4.4,2.25) 5(-4.4,1.75) 6(-4.4,1.25) 7(-4.4,0.75) 8(-4.4,0.25) 9(-4.4,-0.25) 10(-4.4,-0.75) 11(-4.4,-1.25) 12(-4.4,-1.75) 13(-4.4,-2.25) 14(-4.4,-2.75) 15(-4.4,-3.25) 16(-4.4,-3.75) 33(4.4,-3.75) 34(4.4,-3.25) 35(4.4,-2.75) 36(4.4,-2.25) 37(4.4,-1.75) 38(4.4,-1.25) 39(4.4,-0.75) 40(4.4,-0.25) 41(4.4,0.25) 42(4.4,0.75) 43(4.4,1.25) 44(4.4,1.75) 45(4.4,2.25) 46(4.4,2.75) 47(4.4,3.25) 48(4.4,3.75)
  rrect100% 0.24x0.6 smd: 17(-3.75,-4.4) 18(-3.25,-4.4) 19(-2.75,-4.4) 20(-2.25,-4.4) 21(-1.75,-4.4) 22(-1.25,-4.4) 23(-0.75,-4.4) 24(-0.25,-4.4) 25(0.25,-4.4) 26(0.75,-4.4) 27(1.25,-4.4) 28(1.75,-4.4) 29(2.25,-4.4) 30(2.75,-4.4) 31(3.25,-4.4) 32(3.75,-4.4) 49(3.75,4.4) 50(3.25,4.4) 51(2.75,4.4) 52(2.25,4.4) 53(1.75,4.4) 54(1.25,4.4) 55(0.75,4.4) 56(0.25,4.4) 57(-0.25,4.4) 58(-0.75,4.4) 59(-1.25,4.4) 60(-1.75,4.4) 61(-2.25,4.4) 62(-2.75,4.4) 63(-3.25,4.4) 64(-3.75,4.4)
  rrect2% 6.3x6.3 smd paste-4: 65(0,0)
  silkscreen extent -4.7,-4.7 4.7,4.7, body extent -4.57,-4.57 4.57,4.57, height 1.02
SAMTEC_HMTSW-102-07-G-S-240 [mm] "Header, 2.54mm, 2x1, TH"
  rect 1.55x1.55 hole 1.02: 1(-1.27,0)
  round 1.55 hole 1.02: 2(1.27,0)
  silkscreen extent -2.54,-1.24 2.54,2.54, body extent -2.54,-1.27 2.54,1.27, height 8.64
SML-31_Red [mm] "Rohm"
  rect 0.8x0.8 smd: 1(-0.825,0) 2(0.825,0)
  silkscreen extent -1.93,-0.76 1.1,0.76, body extent -0.85,-0.45 0.85,0.45, height 0.91
SOD-123 [mm] "On Semi recommended land pattern"
  rect 0.915x1.22 smd: 1(-1.637,0) 2(1.637,0)
  silkscreen extent -2.74,-1.17 2.03,1.17, body extent -1.93,-0.9 1.93,0.9, height 1.35
SOP-8_150MIL [mm] "SOP, 8-Leads, Body 5.03x4mm, Pitch 1.27mm"
  rrect18% 1.4x0.57 smd: 1(-2.75,1.905) 2(-2.75,0.635) 3(-2.75,-0.635) 4(-2.75,-1.905) 5(2.75,-1.905) 6(2.75,-0.635) 7(2.75,0.635) 8(2.75,1.905)
  silkscreen extent -2,-2.5 2,2.79, body extent -2,-2.5 2,2.5, height 1.76
SOT-23 [mm] "SOT23, 3-Leads, Body 2.9x1.3mm, Pitch 0.95mm, Lead Span 2.5mm, IPC Medium Density"
  rrect50% 1x0.6 smd: 1(-1.2,0.95) 2(-1.2,-0.95) 3(1.2,0)
  silkscreen extent -1.62,-1.5 0.7,1.5, body extent -1.16,-1.45 1.21,1.45, height 1
Sullins_GRPB032VWVN-RC [mm] "Sullins"
  rect 1.05x1.05 hole 0.7 paste+0: 1(-0.635,1.27)
  round 1.05 hole 0.7 paste+0: 2(0.635,1.27) 3(-0.635,0) 4(0.635,0) 5(-0.635,-1.27) 6(0.635,-1.27)
  silkscreen extent -1.85,-2.15 1.85,2.66, body extent -1.85,-2.15 1.85,2.15, height 4
Sullins_GRPB041VWVN-RC [mm] "TH, Header, 1.27 mm, 4x1, Straight"
  rect 1.05x1.05 hole 0.75: 1(-1.905,0)
  round 1.05 hole 0.75: 2(-0.635,0)
  round 1.05 hole 0.75 mask+0.064: 3(0.635,0) 4(1.905,0)
  silkscreen extent -3.54,-1.07 2.79,1.07, body extent -2.79,-1.07 2.79,1.07, height 4.3
SW_EVQ-PSD02K [mm] "Panasonic"
  rect 1x1.3 smd: 1(-1.7,2.15) 2(-1.7,-2.15) 3(1.7,-2.15) 4(1.7,2.15)
  round 0.5 hole 1 unplated mask+0.381: MH1(-1.5,0) MH2(1.5,0)
  body extent -3.05,-2.3 4.35,2.3, height 1.8
SW_MJTP1117 [mm] "TH, 2-Leads, Body 7.3x5.9mm, Pitch 5mm"
  round 1.5 hole 1: 1(-2.5,1.97) 2(2.5,1.97)
  round 1.8 hole 1.3: MH1(-3.5,4.47) MH2(3.5,4.47)
  silkscreen extent -3.65,0.15 3.65,5.9, body extent -3.95,-1.45 3.95,5.9, height 4.3
TAYO_AH316M [mm] "SMD, 2-Leads, Body 3.2x1.6mm"
  rect 1x1.2 smd: 1(-1.6,0) 2(1.6,0)
  silkscreen extent -2.73,-0.87 0.9,0.87, body extent -1.68,-0.87 1.68,0.87, height 0.61
TC2050-IDC-430-FP [mil] "TAG-CONNECT"
  round 31 smd paste-16: 1(-25,100) 2(-25,50) 3(-25,0) 4(-25,-50) 5(-25,-100) 6(25,-100) 7(25,-50) 8(25,0) 9(25,50) 10(25,100)
  round 31 hole 39 unplated mask+8: MH1(0,150) MH2(-40,-150) MH3(40,-150)
  silkscreen extent -135,-265 135,251
TDK_DEA202450BT-1294C1-H [mm] "SMD, 4-Leads, Body 2x1.25mm"
  rect 0.35x0.35 smd: 1(0,0.325) 3(0,-0.325)
  rect 0.45x1 smd paste-1.016: 2(0.65,0) 4(-0.65,0)
  silkscreen extent -1.17,-0.8 1.17,1, body extent -1.07,-0.67 1.07,0.67, height 0.8
TI_Stacked_Overlay_Small [mil]
  silkscreen extent -293,-69 293,69
TP_H045P075#1 [mm] "TP_H0.45P0.75"
  round 0.75 hole 0.45 mask+0.064: 1(0,0)
TP_H045P075#2 [mm] "TP_H0.45P0.75"
  round 0.75 hole 0.45: 1(0,0)
TSW-103-07-G-S [mm] "Samtec 100mil, 1x3, 230 mil above insulator"
  rect 1.65x1.65 hole 1.016 mask+0.064: 1(-2.54,0)
  round 1.65 hole 1.016 mask+0.064: 2(0,0) 3(2.54,0)
  silkscreen extent -3.81,-2.03 3.81,1.27, body extent -3.81,-1.27 3.81,1.27, height 8.38
WL-SMCW_GREEN [mm] "WURTH"
  rect 0.8x0.8 smd: 1(-0.8,0) 2(0.8,0)
  silkscreen extent -1.9,-0.8 1.2,0.8, body extent -0.85,-0.45 0.85,0.45, height 0.8
WL-SMCW_RED [mm] "WURTH"
  rect 0.8x0.8 smd: 1(-0.8,0) 2(0.8,0)
  silkscreen extent -1.9,-0.8 1.2,0.8, body extent -0.85,-0.45 0.85,0.45, height 0.8
WL-SMCW_YELLOW [mm] "WURTH"
  rect 0.8x0.8 smd: 1(-0.8,0) 2(0.8,0)
  silkscreen extent -1.9,-0.8 1.2,0.8, body extent -0.85,-0.45 0.85,0.45, height 0.8
XTAL_ABS07 [mm] "ABRACON"
  rect 1.1x1.9 smd: 1(-1.25,0) 2(1.25,0)
  silkscreen extent -0.4,-1 0.4,1, body extent -1.65,-0.8 1.65,0.8, height 0.9

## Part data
C1 C22 C24: "CAP, CERM, 10 pF, 50 V, +/- 5%, C0G/NP0, 0402"
C2: "CAP, CERM, 0.5 pF, 50 V, +/- 20%, C0G/NP0, 0402"
C3 C5 C7 C8 C9 C10 C14 C15 C17 C18 C23 C27: "CAP, CERM, 0.1 µF, 10 V, +/- 10%, X5R, 0402"
C4 C16 C21: "CAP, CERM, 10 µF, 6.3 V, +/- 20%, X5R, 0603"
C6: "CAP, CERM, 1 µF, 10 V, +/- 10%, X5R, 0402"
C11 C12 C13: "CAP, CERM, 4.7 µF, 6.3 V, +/- 20%, X5R, 0402"
C19 C20: "CAP, CERM, 22 µF, 4 V, +/- 20%, X5R, 0603"
C25 C26: "CAP, CERM, 6.2 pF, 50 V, +/- 5%, C0G/NP0, 0402"
C28: "CAP, CERM, 15 pF, 50 V, +/- 5%, C0G/NP0, 0402"
C29 C32: "CAP, CERM, 10 µF, 10 V, +/- 10%, X5R, 0805"
C30 C31: "CAP, CERM, 100 µF, 6.3 V, +/- 20%, X5R, 1206"
C33: "CAP, CERM, 1000 pF, 50 V, +/- 10%, X5R, 0603"
D1 D2: "Diode, Schottky, 30 V, 1 A, SOD-123"
D3 D4: "LED, Red, SMD"
D5: "LED, Green, SMD"
D6: "LED, Yellow, SMD"
D7: "Diode, Schottky, 45 V, 0.03 A, 0603 Diode"
E1: "ANT BLUETOOTH W-LAN ZIGBEE WIMAX, SMD"
FID1 FID2 FID3 FID4 FID5 FID6: "Fiducial mark.  There is nothing to buy or mount."
FL1: "Multilayer Chip Band Pass Filter For 2.4GHz W-LAN/Bluetooth, SMD"
J1: "Connector, Ultra-Mini Coaxial, SMD"
J2: "Coaxial Connectors with Switch, 50 Ohm, SMD"
J3: "Footprint for TC2050-IDC-430"
J4: "Header, 50mil, 3x2, Gold, TH"
J5: "Header, 50mil, 4x1, Gold, TH"
J6: "Connector, Receptacle, Micro-USB Type B, R/A, Bottom Mount SMT"
J7: "Header, 100mil, 3x1, Gold, TH"
J8: "Header, 100mil, 2x1, Gold, TH"
L1: library part LQG15HS3N3S02D, "Inductor, Multilayer, Air Core, 3.3 nH, 0.3 A, 0.17 ohm, SMD"
L2 L4: "Inductor, Multilayer, Ferrite, 2.2 µH, 1.3 A, 0.08 ohm, SMD"
L3: "Inductor, Multilayer, Ferrite, 1 µH, 1.6 A, 0.055 ohm, SMD"
L5 L6: "Ferrite Bead, 30 ohm @ 100 MHz, 1.5 A, 0805"
LBL1: library part THT-14-423-10, "Thermal Transfer Printable Labels, 0.650\" W x 0.200\" H - 10,000 per roll"
Logo1: library part TI_Logo, "Texas Instrument Corporate Signature"
Logo2: library part Pb-Free
Logo3: library part FCC_disclaimer, "FCC_disclaimer"
Logo4 Logo5: library part ESD_Susceptible, "ESD Susceptible Symbol"
P1 P2 P3 P4: "Connector, Receptacle, 100mil, 10x1, Gold plated, TH"
Q1 Q2 Q3: "MOSFET, N-CH, 50 V, 0.22 A, SOT-23"
R1 R2 R12 R13 R17 R19 R21 R29 R30 R31 R32 R33 R34 R35 R36 R37 R39 R40 R41 R42 R43 R45 R46 R47: "RES, 0, 5%, 0.063 W, 0402"
R3 R56 R59 R60: "RES, 10 k, 5%, 0.063 W, 0402"
R4 R5 R6 R10 R55: "RES, 0, 5%, 0.1 W, 0603"
R7 R8 R9 R11 R14 R15 R16 R20 R23 R24 R25 R26 R27 R52: "RES, 100 k, 5%, 0.063 W, 0402"
R18 R22 R38 R44: "RES, 1.0 k, 5%, 0.063 W, 0402"
R28: "RES, 100 k, 1%, 0.1 W, 0603"
R48: "RES, 0.1, 1%, 0.25 W, 0805"
R49 R54 R57: "RES, 270, 5%, 0.1 W, 0603"
R50: "RES, 51 k, 5%, 0.063 W, 0402"
R51: "RES, 30.1 k, 1%, 0.063 W, 0402"
R53 R61 R62: "RES, 100, 1%, 0.1 W, 0402"
R58: "RES, 220, 5%, 0.1 W, 0603"
SW1: "Switch, Tactile, SPST-NO, SMT"
SW2 SW3: "Switch, SPST-NO, Off-Mom, 1 Pos, 0.05A, 12VDC, TH"
TP1 TP2 TP3 TP4 TP5: library part TP_H0.45P0.75, "Testpoint"
U1: "ULTRA LOW POWER, 16M-BIT [x 1/x 2/x 4] CMOS MXSMIO(SERIAL MULTI I/O) FLASH MEMORY, SOP-8"
U2: "SimpleLink Wi-Fi Network Processor, Internet-of-Things Solution for MCU Applications, RGK0064B (VQFN-64)"
U3: "Ultralow-Noise, High PSRR, Fast, RF, 1A, Low-Dropout Linear Regulator, DCQ0006A"
Y1: "CRYSTAL, 32.768KHZ, 9PF, SMD"
Y2: "Low Power Clock Oscillator, 32.768 kHz, SMD"
Y3: "Crystal, 40MHz, 8pF, SMD"
ZZ2 ZZ3 ZZ4: library part AssemblyNote

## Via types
v1: diameter 24, hole 12, Top Layer to Bottom Layer, tented both sides, 224 vias
v2: diameter 24, hole 12.1, Top Layer to Bottom Layer, 36 vias
v3: diameter 30, hole 16, Top Layer to Bottom Layer, tented both sides, 23 vias
v4: diameter 40, hole 20, Top Layer to Bottom Layer, 9 vias

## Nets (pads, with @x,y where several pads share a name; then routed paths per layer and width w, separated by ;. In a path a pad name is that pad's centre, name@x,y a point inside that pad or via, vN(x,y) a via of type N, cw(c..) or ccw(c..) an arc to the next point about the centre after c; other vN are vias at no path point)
CC_IRQ: R16.1 R31.2 U2.15 | length 452.2
  Top Layer w6: U2.15@1428.23,967.95 1450.45,967.95 1515.7,1033.2 1536.82,1033.2 R16.1@1650,1146.38 1671.38,1146.38 1749,1224 R31.2@1774.38,1224
CC_NHIB: R28.1 R38.1 R59.1 SW2.2 U2.2 | length 3044.9
  Top Layer w8: SW2.2@96.99,105.44 40.4,162.03 40.4,660.4 174,794 384,794 404,774 486.62,774 R38.1@510.62,798 531.8,798 542.53,787.27 R28.1@542.53,741.22 576.88,741.22 625.4,692.7 625.4,615.7 607.2,597.5 585.9,597.5 567,578.6 489.1,578.6 411.78,501.28 R59.1@411.78,399.3 ; U2.2@1428.23,712.05 1446.95,712.05 1455.12,703.88 v1(1455.12,664.88)
  Bottom Layer w6: v1(601.5,597.8) 628.6,570.7 628.6,540 787.6,381 937.8,381 993.7,436.9 1065.97,436.9 1160.27,531.2 1194.1,531.2 1221,504.3 1221,478.1 1240.23,458.87 1375.17,458.87 1410,493.7 1410,619.76 v1(1455.12,664.88)
CC_NRESET: C27.1 D7.2 R26.2 R60.1 SW3.2 U2.32 | length 1483.8
  Top Layer w6: R26.2@988.6,1190 R26.2@989.02,1190
  Top Layer w8: C27.1@988.6,1147.49 R26.2@988.6,1190 ; R26.2@989.02,1190 v1(1025,1190) 1060,1155 1060,1082 1107.32,1034.67 U2.32@1107.32,1013.23
  Top Layer w10: v1(1230,1288) 1248.2,1288 1339.4,1379.2 1339.4,1531.9 1423.67,1616.17 1652.68,1616.17 1673.12,1595.73 R60.1@1673.12,1593 D7.2@1738.68,1593 1797.5,1593 1807.28,1602.78 SW3.2@1912.12,1602.78
  Bottom Layer w10: v1(1025,1190) 1046.6,1211.6 1197.4,1211.6 1230,1244.2 v1(1230,1288)
CC_NWP_UART_TX: R40.1 U2.62 | length 555.3
  Top Layer w6: U2.62@1363.27,666.77 1363.29,642.14 1394.49,610.95 1405.89,610.95 1423.84,593 1437.02,593 v1(1470.43,559.6) ; v1(1584.6,671.4) 1589.6,671.4 1624.2,636.8 1747.8,636.8 1769,658 R40.1@1790.38,658
  Bottom Layer w6: v1(1470.43,559.6) 1472.8,559.6 v1(1584.6,671.4)
CC_SPI_CLK: R42.1 U2.5 | length 1585.4
  Top Layer w6: U2.5@1428.23,771.1 1437.71,771.1 1498.7,710.11 v1(1498.7,673.34)
  Top Layer w8: R42.1@464.72,671.74 471.21,671.74 v1(513.9,629.05)
  Bottom Layer w6: v1(513.9,629.05) 513.9,540.9 581.2,473.6 672.8,473.6 788.4,358 944.5,358 1009.3,422.8 1068.84,422.8 1131.54,485.5 1165.4,485.5 1204.03,446.87 1399.69,446.87 1424.27,471.45 1424.27,598.91 v1(1498.7,673.34)
CC_SPI_CS: R32.2 U2.8 | length 712.1
  Top Layer w6: U2.8@1428.23,830.16 1482.57,830.16 1490.37,822.36 1510.98,822.36 1557.65,775.69 1567.52,775.69 v1(1590.27,752.94) ; v1(1695,1130) 1739,1174 R32.2@1774.38,1174
  Bottom Layer w6: v1(1590.27,752.94) 1695,857.67 v1(1695,1130)
CC_SPI_DIN: R39.2 U2.6 | length 442.3
  Top Layer w6: U2.6@1428.23,790.79 1436.64,790.79 1529.63,697.81 1529.63,686.68 1576.34,639.96 1601.04,639.96 1628,613 R39.2@1790.38,613
CC_SPI_DOUT: R15.1 R41.2 U2.7 | length 315.3
  Top Layer w6: U2.7@1428.23,810.47 1435.04,810.47 1435.15,810.36 1506.01,810.36 1563.98,752.39 1563.98,727.4 R15.1@1571.38,720 1629.38,662 R41.2@1667.38,662
CC_UART1_CTS: R34.1 U2.61 | length 1040.6
  Top Layer w6: U2.61@1343.58,666.77 1343.6,638.72 1383.38,598.95 1400.92,598.95 1489.6,510.27 1489.6,500.42 v1(1510.02,480) ; v1(1738.38,1124) R34.1@1774.38,1124
  Bottom Layer w6: v1(1510.02,480) 1510.02,531.42 1738.38,759.78 v1(1738.38,1124)
CC_UART1_RTS: R11.1 R36.1 U2.50 | length 1772.3
  Top Layer w6: U2.50@1127.05,666.77 1127.01,637.96 1112.96,623.9 1112.96,508.16 1104.52,499.72 R11.1@1104.52,477.7 1117.52,464.7 v1@1137.5,464.7 ; v1(1140.8,464.5) 1137.7,464.5 v1@1137.5,464.7 ; v1@1141,464.7 v1@1137.5,464.7 ; v1(1733,1369) R36.1@1774.38,1369
  Bottom Layer w6: v1(1140.8,464.5) 1176.6,428.7 1571.6,428.7 1593.6,450.7 1593.6,572.6 1774.7,753.7 1774.7,1327.3 v1(1733,1369)
CC_UART1_RX: R9.2 R35.1 U2.57 | length 1474.5
  Top Layer w6: R35.1@509.62,848 511.62,850 v1(590,850) ; U2.57@1264.84,666.77 1264.84,648.8 1332.08,581.56 R9.2@1332.08,529.34 1332.08,500.41 v1(1315.36,483.69)
  Bottom Layer w6: v1(590,850) 644.3,795.7 644.3,546.2 796.7,393.8 917.8,393.8 975.5,451.5 1063.6,451.5 1162.1,550 1288,550 1315.36,522.64 v1(1315.36,483.69)
CC_UART1_TX: R8.2 R33.1 U2.55 | length 1532.1
  Top Layer w6: R33.1@509.62,898 541,898 548,905 603.7,905 v1(605.26,903.44) ; U2.55@1225.59,666.65 U2.55@1225.47,666.77 1225.46,625.53 1233,618 1233,616 v1(1236,613) ; v1(1355,479.87) 1355.13,479.87 1366.38,468.62 R8.2@1366.38,450
  Bottom Layer w6: v1(605.26,903.44) 644.06,903.44 679,868.5 679,533.9 800.4,412.5 906.97,412.5 1060.47,566 1189,566 v1(1236,613) 1311.7,613 1355,569.7 v1(1355,479.87)
CC_WL_UART_TX: R43.1 U2.60 | length 652.4
  Top Layer w6: U2.60@1323.9,666.77 1323.9,641.46 1378.41,586.95 1395.95,586.95 1477.6,505.3 1477.6,479.77 1522.37,435 1630,435 v1(1648,453) ; v1(1754.38,568) R43.1@1790.38,568
  Bottom Layer w6: v1(1648,453) 1722.38,527.38 1722.38,536 v1(1754.38,568)
CC_WLRS232_RX: R46.1 U2.59 | length 640.4
  Top Layer w6: U2.59@1304.21,666.77 1304.21,644.18 1373.44,574.95 1390.98,574.95 1465.6,500.33 1465.6,471.6 1520,417.2 1663.73,417.2 v1(1694.7,448.17) ; v1(1754.38,429) R46.1@1790.38,429
  Bottom Layer w6: v1(1694.7,448.17) 1713.86,429 v1(1754.38,429)
CC_WLRS232_TX: R45.1 U2.58 | length 480.4
  Top Layer w6: U2.58@1284.53,666.77 1284.53,646.89 1368.55,562.86 1386.1,562.86 1453.6,495.36 1453.6,464.4 1520.71,397.29 1560.71,397.29 1578,380 R45.1@1616.38,380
